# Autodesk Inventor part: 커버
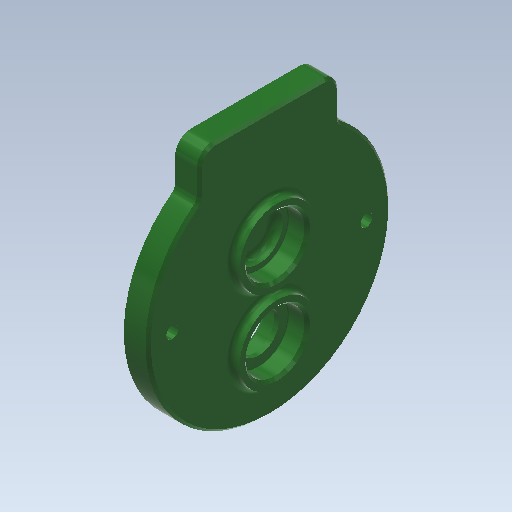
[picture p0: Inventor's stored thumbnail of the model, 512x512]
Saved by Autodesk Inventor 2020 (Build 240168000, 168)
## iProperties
Created: 2016-02
Part Number: 커버
Material: 알루미늄 6061
Document SubType Name: Modeling
Designer: mduedu
Density: 2.71 g/cm^3
Appearance: 매끄러움 - 짙은 산림 녹색
Author: mduedu
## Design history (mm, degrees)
sketch "스케치1"
  geometry: C1 r 45 at (0, 0); 1 further point
  constraints: 1 centre point, 1 coincident
  dimensions: "d0" = 90 diameter of C1
extrude "돌출1" new body sketch "스케치1" distance "d1" = 9; taper "d2" = 0 deg
sketch "스케치2"
  geometry: C1 r 14 at (0, 11); 1 further point
  constraints: 1 centre point, 1 vertical alignment
  dimensions: "d3" = 28 diameter of C1; "d6" = 11 distance of C1.centre point (0, 0)
extrude "돌출2" join sketch "스케치2" distance "d7" = 3; taper "d8" = 0 deg
sketch "스케치3"
  geometry: C1 r 14 at (0, -20); 1 further point
  constraints: 1 centre point, 1 vertical alignment
  dimensions: "d9" = 28 diameter of C1; "d10" = 20 distance of C1.centre point (0, 0)
extrude "돌출3" join sketch "스케치3" distance "d11" = 3; taper "d12" = 0 deg
hole "구멍1" diameter "d15" = 22; stored, may be unused: countersink angle "d19" = 90 deg, drill point angle "d21" = 0 deg; dims "d13" = 10, "d14" = 10, "d16" = 6, "d17" = 4, "d18" = 2, "d20" = 7
hole "구멍2" diameter "d24" = 18; stored, may be unused: countersink angle "d28" = 90 deg, drill point angle "d30" = 0 deg; dims "d25" = 6, "d26" = 4, "d27" = 2, "d29" = 3, "d107" = 10, "d108" = 10
hole "구멍3" diameter "d33" = 22; stored, may be unused: countersink angle "d37" = 90 deg, drill point angle "d39" = 0 deg; dims "d34" = 6, "d35" = 4, "d36" = 2, "d38" = 7, "d73" = 10, "d74" = 10
sketch "스케치7"
  geometry: L1 (-26, 36.729)-(26, 36.729); L2 (26, 36.729)-(26, 53); L3 (26, 53)-(-26, 53); L4 (-26, 53)-(-26, 36.729); A1 r 45 centre (0, 0) between (-26, 36.729) and (26, 36.729) reference; 1 further point
  constraints: 8 end point, 2 parallel, 2 point on circle, 1 horizontal, 1 perpendicular
  dimensions: "d95" = 52 distance of L2.end L3.end; "d97" = 53 distance from line of L3 point (0, 0)
extrude "돌출5" join sketch "스케치7" stored distance "d98" = 10; taper "d99" = 0 deg
sketch "스케치4"
  geometry: C1 r 14 at (0, -20) reference; C2 r 18 at (0, -20); 1 further point
  constraints: 1 centre point, 1 coincident
  dimensions: "d40" = 36 diameter of C2
extrude "돌출4" join sketch "스케치4" distance "d41" = 4; taper "d42" = 0 deg
hole "구멍4" diameter "d45" = 22; stored, may be unused: countersink angle "d49" = 90 deg, drill point angle "d51" = 0 deg; dims "d46" = 6, "d47" = 4, "d48" = 2, "d50" = 7.3, "d102" = 10, "d103" = 10
chamfer "모따기3" distance "d104" = 0.7; stored, may be unused: second distance "d105" = 2, angle "d106" = 30 deg
hole "구멍5" diameter "d54" = 15; stored, may be unused: countersink angle "d58" = 90 deg, drill point angle "d60" = 0 deg; dims "d52" = 10, "d53" = 10, "d55" = 6, "d56" = 4, "d57" = 2, "d59" = 7
fillet "모깎기1" dims "d61" = 0.3
fillet "모깎기2" dims "d62" = 3
chamfer "모따기1" distance "d63" = 1; stored, may be unused: second distance "d64" = 2, angle "d65" = 45 deg
fillet "모깎기6" dims "d88" = 2
sketch "스케치5" dims "d67" = 72
  geometry: 4 further points
  constraints: 2 horizontal alignment, 1 coincident, 5 other
  dimensions: "d71" = 360 deg dimension on point (0, 0) point (-36, 0) (derived)
fillet "모깎기4" dims "d75" = 2
sketch "스케치6"
  geometry: 2 further points
hole "구멍6" sketch "스케치6" at (36, 0), (-36, 0) diameter "d76" = 4.5; stored, may be unused: countersink angle "d80" = 90 deg, drill point angle "d82" = 0 deg; dims "d77" = 6, "d78" = 8, "d79" = 4.6, "d81" = 8
fillet "모깎기7" dims "d100" = 6, "d101" = 3
chamfer "모따기2" distance "d90" = 1; stored, may be unused: second distance "d91" = 2, angle "d92" = 45 deg
node "솔리드1"
node "절단 모서리 투영1"
